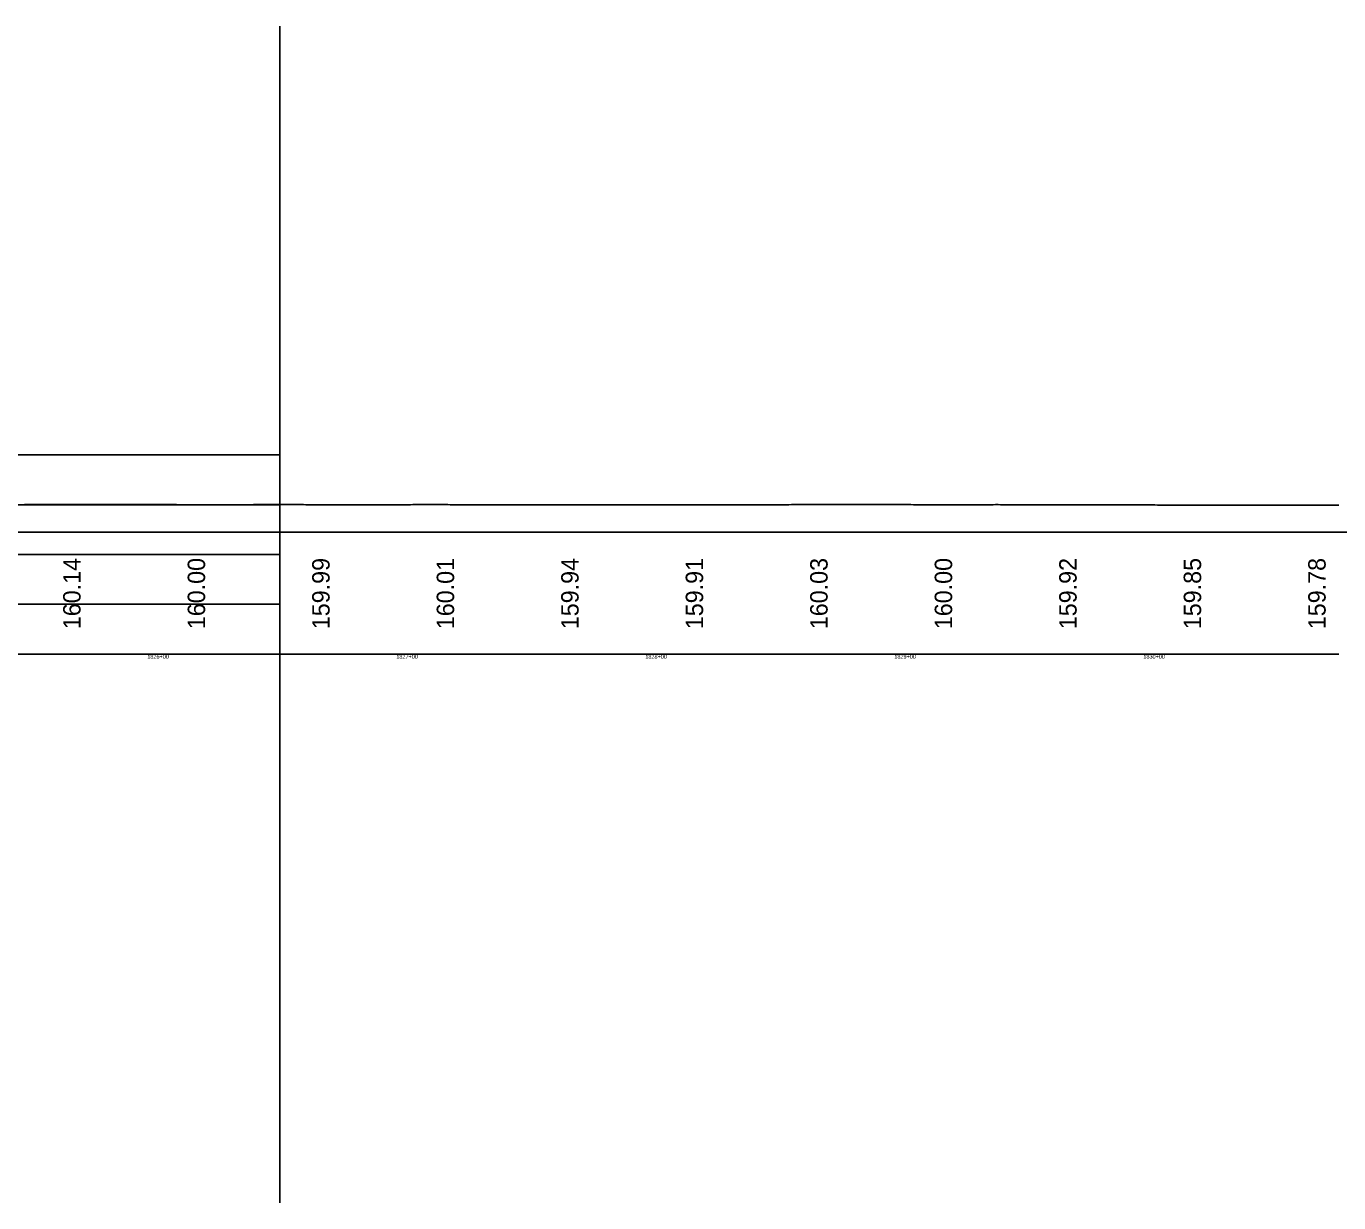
# Model space of a CAD drawing. Extents: x 2126510 to 2136144, y 865066 to 868066.
# Drawn here: x 2130996 to 2131523, y 866394 to 866866 of the extents above; entities that cross this region are included whole.
import ezdxf

# ---------------------------------------------------------------- set-up
doc = ezdxf.new("R2010")
doc.units = 0
doc.layers.add('RD_EX_GuardRail', color=7, linetype='Continuous')
doc.layers.add('RD_EX_Misc', color=7, linetype='Continuous')

msp = doc.modelspace()

# ---------------------------------------------------------------- linework, layer by layer
at = {"layer": 'RD_EX_GuardRail'}
for p, q in [((2131097.7, 866866.08), (2131097.7, 866393.55)), ((2131097.7, 866693.9), (2126517.45, 866693.9)), ((2131097.7, 866673.9), (2129000.13, 866673.9)), ((2131097.7, 866653.9), (2126517.45, 866653.9)), ((2131097.7, 866633.9), (2126517.45, 866633.9)), ((2131097.7, 866613.9), (2126517.45, 866613.9))]:
    msp.add_line(p, q, dxfattribs=at)
at = {"layer": 'RD_EX_Misc'}
msp.add_line((2127368.72, 866613.9), (2131522.97, 866613.9), dxfattribs=at)
for points in [[(2130995.19, 866674.02), (2130996.19, 866674.03), (2130997.19, 866674.03), (2130998.19, 866674.03), (2130999.19, 866674.03), (2131000.19, 866674.03), (2131001.19, 866674.03), (2131002.19, 866674.03), (2131003.19, 866674.03), (2131004.19, 866674.03), (2131005.19, 866674.03), (2131006.19, 866674.04), (2131007.19, 866674.04), (2131008.19, 866674.04), (2131009.19, 866674.04), (2131010.19, 866674.04), (2131011.19, 866674.04), (2131012.19, 866674.04), (2131013.19, 866674.04), (2131014.19, 866674.04), (2131015.19, 866674.04), (2131016.19, 866674.04), (2131017.19, 866674.04), (2131018.19, 866674.04), (2131019.19, 866674.05), (2131020.19, 866674.05), (2131021.19, 866674.05), (2131022.19, 866674.05), (2131023.19, 866674.05), (2131024.19, 866674.05), (2131025.19, 866674.05), (2131026.19, 866674.04), (2131027.19, 866674.04), (2131028.19, 866674.03), (2131029.19, 866674.03), (2131030.19, 866674.03), (2131031.19, 866674.02), (2131032.19, 866674.02)], [(2131032.19, 866674.02), (2131033.19, 866674.01), (2131034.19, 866674.01), (2131035.19, 866674), (2131036.19, 866674), (2131037.19, 866673.99), (2131038.19, 866673.99), (2131039.19, 866673.98), (2131040.19, 866673.98), (2131041.19, 866673.97), (2131042.19, 866673.97), (2131043.19, 866673.97), (2131044.19, 866673.96), (2131045.19, 866673.96), (2131046.19, 866673.95), (2131047.19, 866673.95), (2131048.19, 866673.95), (2131049.19, 866673.94), (2131050.19, 866673.94), (2131051.19, 866673.94), (2131052.19, 866673.94), (2131053.19, 866673.93), (2131054.19, 866673.93), (2131055.19, 866673.93), (2131056.19, 866673.93), (2131057.19, 866673.92), (2131058.19, 866673.92), (2131059.19, 866673.92), (2131060.19, 866673.91), (2131061.19, 866673.91), (2131062.19, 866673.91), (2131063.19, 866673.91), (2131064.19, 866673.9), (2131065.19, 866673.9), (2131066.19, 866673.9), (2131067.19, 866673.91), (2131068.19, 866673.91), (2131069.19, 866673.91), (2131070.19, 866673.91), (2131071.19, 866673.91), (2131072.19, 866673.91), (2131073.19, 866673.91), (2131074.19, 866673.91), (2131075.19, 866673.91), (2131076.19, 866673.91), (2131077.19, 866673.92), (2131078.19, 866673.92), (2131079.19, 866673.92), (2131080.19, 866673.92), (2131081.19, 866673.92), (2131082.19, 866673.92), (2131083.19, 866673.92), (2131084.19, 866673.92), (2131085.19, 866673.92), (2131086.19, 866673.92), (2131087.19, 866673.93), (2131088.19, 866673.93), (2131089.19, 866673.93), (2131090.19, 866673.93), (2131091.19, 866673.93), (2131092.19, 866673.93), (2131093.19, 866673.93), (2131094.19, 866673.93), (2131095.19, 866673.93), (2131096.19, 866673.93), (2131097.19, 866673.94), (2131098.19, 866673.94), (2131099.19, 866673.94), (2131100.19, 866673.94), (2131101.19, 866673.94), (2131102.19, 866673.94), (2131103.19, 866673.94), (2131104.19, 866673.94), (2131105.19, 866673.93), (2131106.19, 866673.93), (2131107.19, 866673.93), (2131108.19, 866673.92), (2131109.19, 866673.92), (2131110.19, 866673.92), (2131111.19, 866673.92), (2131112.19, 866673.91), (2131113.19, 866673.91), (2131114.19, 866673.91), (2131115.19, 866673.9), (2131116.19, 866673.9), (2131117.19, 866673.9), (2131118.19, 866673.89), (2131119.19, 866673.89), (2131120.19, 866673.89), (2131121.19, 866673.88), (2131122.19, 866673.88), (2131123.19, 866673.88), (2131124.19, 866673.88), (2131125.19, 866673.88), (2131126.19, 866673.88), (2131127.19, 866673.88), (2131128.19, 866673.88), (2131129.19, 866673.89), (2131130.19, 866673.89), (2131131.19, 866673.89), (2131132.19, 866673.89)], [(2131132.19, 866673.89), (2131133.19, 866673.89), (2131134.19, 866673.9), (2131135.19, 866673.9), (2131136.19, 866673.9), (2131137.19, 866673.9), (2131138.19, 866673.91), (2131139.19, 866673.91), (2131140.19, 866673.91), (2131141.19, 866673.91), (2131142.19, 866673.91), (2131143.19, 866673.92), (2131144.19, 866673.92), (2131145.19, 866673.92), (2131146.19, 866673.92), (2131147.19, 866673.92), (2131148.19, 866673.92), (2131149.19, 866673.92), (2131150.19, 866673.92), (2131151.19, 866673.93), (2131152.19, 866673.93), (2131153.19, 866673.93), (2131154.19, 866673.93), (2131155.19, 866673.93), (2131156.19, 866673.93), (2131157.19, 866673.93), (2131158.19, 866673.93), (2131159.19, 866673.94), (2131160.19, 866673.94), (2131161.19, 866673.94), (2131162.19, 866673.94), (2131163.19, 866673.93), (2131164.19, 866673.93), (2131165.19, 866673.93), (2131166.19, 866673.92), (2131167.19, 866673.92), (2131168.19, 866673.91), (2131169.19, 866673.91), (2131170.19, 866673.91), (2131171.19, 866673.9), (2131172.19, 866673.9), (2131173.19, 866673.89), (2131174.19, 866673.89), (2131175.19, 866673.88), (2131176.19, 866673.88), (2131177.19, 866673.88), (2131178.19, 866673.87), (2131179.19, 866673.87), (2131180.19, 866673.86), (2131181.19, 866673.86), (2131182.19, 866673.86), (2131183.19, 866673.85), (2131184.19, 866673.85), (2131185.19, 866673.85), (2131186.19, 866673.85), (2131187.19, 866673.85), (2131188.19, 866673.84), (2131189.19, 866673.84), (2131190.19, 866673.84), (2131191.19, 866673.84), (2131192.19, 866673.84), (2131193.19, 866673.83), (2131194.19, 866673.83), (2131195.19, 866673.83), (2131196.19, 866673.83), (2131197.19, 866673.83), (2131198.19, 866673.82), (2131199.19, 866673.82), (2131200.19, 866673.82), (2131201.19, 866673.82), (2131202.19, 866673.81), (2131203.19, 866673.81), (2131204.19, 866673.81), (2131205.19, 866673.81), (2131206.19, 866673.81), (2131207.19, 866673.82), (2131208.19, 866673.82), (2131209.19, 866673.82), (2131210.19, 866673.82), (2131211.19, 866673.82), (2131212.19, 866673.83), (2131213.19, 866673.83), (2131214.19, 866673.83), (2131215.19, 866673.83), (2131216.19, 866673.83), (2131217.19, 866673.84), (2131218.19, 866673.84), (2131219.19, 866673.84), (2131220.19, 866673.84), (2131221.19, 866673.84), (2131222.19, 866673.84), (2131223.19, 866673.84), (2131224.19, 866673.84), (2131225.19, 866673.84), (2131226.19, 866673.84), (2131227.19, 866673.84), (2131228.19, 866673.84), (2131229.19, 866673.84), (2131230.19, 866673.84), (2131231.19, 866673.84), (2131232.19, 866673.83)], [(2131232.19, 866673.83), (2131233.19, 866673.83), (2131234.19, 866673.83), (2131235.19, 866673.83), (2131236.19, 866673.83), (2131237.19, 866673.83), (2131238.19, 866673.83), (2131239.19, 866673.83), (2131240.19, 866673.83), (2131241.19, 866673.82), (2131242.19, 866673.82), (2131243.19, 866673.82), (2131244.19, 866673.82), (2131245.19, 866673.82), (2131246.19, 866673.82), (2131247.19, 866673.82), (2131248.19, 866673.82), (2131249.19, 866673.82), (2131250.19, 866673.81), (2131251.19, 866673.81), (2131252.19, 866673.81), (2131253.19, 866673.81), (2131254.19, 866673.81), (2131255.19, 866673.81), (2131256.19, 866673.81), (2131257.19, 866673.81), (2131258.19, 866673.81), (2131259.19, 866673.81), (2131260.19, 866673.81), (2131261.19, 866673.81), (2131262.19, 866673.81), (2131263.19, 866673.81), (2131264.19, 866673.81), (2131265.19, 866673.81), (2131266.19, 866673.81), (2131267.19, 866673.81), (2131268.19, 866673.81), (2131269.19, 866673.81), (2131270.19, 866673.82), (2131271.19, 866673.82), (2131272.19, 866673.82), (2131273.19, 866673.82), (2131274.19, 866673.82), (2131275.19, 866673.82), (2131276.19, 866673.82), (2131277.19, 866673.83), (2131278.19, 866673.83), (2131279.19, 866673.83), (2131280.19, 866673.83), (2131281.19, 866673.83), (2131282.19, 866673.83), (2131283.19, 866673.84), (2131284.19, 866673.84), (2131285.19, 866673.84), (2131286.19, 866673.84), (2131287.19, 866673.85), (2131288.19, 866673.85), (2131289.19, 866673.86), (2131290.19, 866673.86), (2131291.19, 866673.87), (2131292.19, 866673.87), (2131293.19, 866673.88), (2131294.19, 866673.88), (2131295.19, 866673.89), (2131296.19, 866673.89), (2131297.19, 866673.9), (2131298.19, 866673.9), (2131299.19, 866673.91), (2131300.19, 866673.91), (2131301.19, 866673.92), (2131302.19, 866673.92), (2131303.19, 866673.93), (2131304.19, 866673.93), (2131305.19, 866673.93), (2131306.19, 866673.93), (2131307.19, 866673.93), (2131308.19, 866673.93), (2131309.19, 866673.93), (2131310.19, 866673.93), (2131311.19, 866673.93), (2131312.19, 866673.93), (2131313.19, 866673.93), (2131314.19, 866673.93), (2131315.19, 866673.93), (2131316.19, 866673.93), (2131317.19, 866673.93), (2131318.19, 866673.93), (2131319.19, 866673.93), (2131320.19, 866673.93), (2131321.19, 866673.93), (2131322.19, 866673.94), (2131323.19, 866673.94), (2131324.19, 866673.94), (2131325.19, 866673.94), (2131326.19, 866673.94), (2131327.19, 866673.94), (2131328.19, 866673.94), (2131329.19, 866673.94), (2131330.19, 866673.94), (2131331.19, 866673.94), (2131332.19, 866673.94)], [(2131332.19, 866673.94), (2131333.19, 866673.94), (2131334.19, 866673.94), (2131335.19, 866673.94), (2131336.19, 866673.94), (2131337.19, 866673.94), (2131338.19, 866673.94), (2131339.19, 866673.94), (2131340.19, 866673.95), (2131341.19, 866673.95), (2131342.19, 866673.95), (2131343.19, 866673.94), (2131344.19, 866673.94), (2131345.19, 866673.94), (2131346.19, 866673.94), (2131347.19, 866673.94), (2131348.19, 866673.93), (2131349.19, 866673.93), (2131350.19, 866673.93), (2131351.19, 866673.93), (2131352.19, 866673.92), (2131353.19, 866673.92), (2131354.19, 866673.92), (2131355.19, 866673.92), (2131356.19, 866673.91), (2131357.19, 866673.91), (2131358.19, 866673.91), (2131359.19, 866673.91), (2131360.19, 866673.91), (2131361.19, 866673.9), (2131362.19, 866673.9), (2131363.19, 866673.9), (2131364.19, 866673.9), (2131365.19, 866673.9), (2131366.19, 866673.9), (2131367.19, 866673.9), (2131368.19, 866673.9), (2131369.19, 866673.9), (2131370.19, 866673.9), (2131371.19, 866673.9), (2131372.19, 866673.91), (2131373.19, 866673.91), (2131374.19, 866673.91), (2131375.19, 866673.91), (2131376.19, 866673.91), (2131377.19, 866673.91), (2131378.19, 866673.91), (2131379.19, 866673.92), (2131380.19, 866673.92), (2131381.19, 866673.92), (2131382.19, 866673.92), (2131383.19, 866673.92), (2131384.19, 866673.92), (2131385.19, 866673.93), (2131386.19, 866673.93), (2131387.19, 866673.92), (2131388.19, 866673.92), (2131389.19, 866673.92), (2131390.19, 866673.91), (2131391.19, 866673.91), (2131392.19, 866673.91), (2131393.19, 866673.9), (2131394.19, 866673.9), (2131395.19, 866673.89), (2131396.19, 866673.89), (2131397.19, 866673.89), (2131398.19, 866673.88), (2131399.19, 866673.88), (2131400.19, 866673.88), (2131401.19, 866673.87), (2131402.19, 866673.87), (2131403.19, 866673.87), (2131404.19, 866673.86), (2131405.19, 866673.86), (2131406.19, 866673.86), (2131407.19, 866673.85), (2131408.19, 866673.85), (2131409.19, 866673.84), (2131410.19, 866673.84), (2131411.19, 866673.84), (2131412.19, 866673.83), (2131413.19, 866673.83), (2131414.19, 866673.83), (2131415.19, 866673.83), (2131416.19, 866673.83), (2131417.19, 866673.82), (2131418.19, 866673.82), (2131419.19, 866673.82), (2131420.19, 866673.81), (2131421.19, 866673.81), (2131422.19, 866673.81), (2131423.19, 866673.81), (2131424.19, 866673.81), (2131425.19, 866673.81), (2131426.19, 866673.81), (2131427.19, 866673.81), (2131428.19, 866673.82), (2131429.19, 866673.82), (2131430.19, 866673.82), (2131431.19, 866673.82), (2131432.19, 866673.82)], [(2131432.19, 866673.82), (2131433.19, 866673.82), (2131434.19, 866673.82), (2131435.19, 866673.82), (2131436.19, 866673.82), (2131437.19, 866673.83), (2131438.19, 866673.83), (2131439.19, 866673.83), (2131440.19, 866673.83), (2131441.19, 866673.83), (2131442.19, 866673.83), (2131443.19, 866673.83), (2131444.19, 866673.82), (2131445.19, 866673.82), (2131446.19, 866673.81), (2131447.19, 866673.81), (2131448.19, 866673.8), (2131449.19, 866673.8), (2131450.19, 866673.79), (2131451.19, 866673.79), (2131452.19, 866673.79), (2131453.19, 866673.78), (2131454.19, 866673.78), (2131455.19, 866673.77), (2131456.19, 866673.77), (2131457.19, 866673.76), (2131458.19, 866673.76), (2131459.19, 866673.75), (2131460.19, 866673.75), (2131461.19, 866673.75), (2131462.19, 866673.75), (2131463.19, 866673.76), (2131464.19, 866673.76), (2131465.19, 866673.76), (2131466.19, 866673.75), (2131467.19, 866673.75), (2131468.19, 866673.75), (2131469.19, 866673.75), (2131470.19, 866673.75), (2131471.19, 866673.75), (2131472.19, 866673.75), (2131473.19, 866673.75), (2131474.19, 866673.74), (2131475.19, 866673.74), (2131476.19, 866673.74), (2131477.19, 866673.74), (2131478.19, 866673.74), (2131479.19, 866673.74), (2131480.19, 866673.74), (2131481.19, 866673.74), (2131482.19, 866673.73), (2131483.19, 866673.73), (2131484.19, 866673.73), (2131485.19, 866673.73), (2131486.19, 866673.73), (2131487.19, 866673.73), (2131488.19, 866673.73), (2131489.19, 866673.73), (2131490.19, 866673.72), (2131491.19, 866673.72), (2131492.19, 866673.72), (2131493.19, 866673.72), (2131494.19, 866673.72), (2131495.19, 866673.72), (2131496.19, 866673.71), (2131497.19, 866673.71), (2131498.19, 866673.71), (2131499.19, 866673.71), (2131500.19, 866673.71), (2131501.19, 866673.71), (2131502.19, 866673.71), (2131503.19, 866673.7), (2131504.19, 866673.7), (2131505.19, 866673.7), (2131506.19, 866673.7), (2131507.19, 866673.7), (2131508.19, 866673.7), (2131509.19, 866673.7), (2131510.19, 866673.69), (2131511.19, 866673.69), (2131512.19, 866673.69), (2131513.19, 866673.69), (2131514.19, 866673.69), (2131515.19, 866673.69), (2131516.19, 866673.69), (2131517.19, 866673.68), (2131518.19, 866673.68), (2131519.19, 866673.68), (2131520.19, 866673.68), (2131521.19, 866673.68), (2131522.19, 866673.68), (2131522.97, 866673.68)], [(2127275.85, 866613.9), (2127275.85, 866662.9), (2131989.68, 866662.9)]]:
    msp.add_lwpolyline(points, dxfattribs=at)

# ---------------------------------------------------------------- texts
for s, p in [('160.14', (2131017.72, 866623.9)), ('160.00', (2131067.72, 866623.9)), ('159.99', (2131117.72, 866623.9)), ('160.01', (2131167.72, 866623.9)), ('159.94', (2131217.72, 866623.9)), ('159.91', (2131267.72, 866623.9)), ('160.03', (2131317.72, 866623.9)), ('160.00', (2131367.72, 866623.9)), ('159.92', (2131417.72, 866623.9)), ('159.85', (2131467.72, 866623.9)), ('159.78', (2131517.72, 866623.9))]:
    msp.add_text(s, height=7, rotation=90, dxfattribs=at).set_placement(p)
for s, p in [('1826+00', (2131044.51, 866612.1)), ('1827+00', (2131144.51, 866612.1)), ('1828+00', (2131244.51, 866612.1)), ('1829+00', (2131344.51, 866612.1)), ('1830+00', (2131444.51, 866612.1))]:
    msp.add_text(s, height=1.6, dxfattribs=at).set_placement(p)

doc.saveas('drawing.dxf')
